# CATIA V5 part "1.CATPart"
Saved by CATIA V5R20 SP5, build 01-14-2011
Part number: 1
Bounding box of the stored display mesh (mm): x -106.5 to -93.5, y -24 to 26, z 3.5 to 16.5
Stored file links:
  F:\CAD\很靠后、\1.CATPart
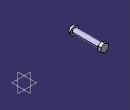
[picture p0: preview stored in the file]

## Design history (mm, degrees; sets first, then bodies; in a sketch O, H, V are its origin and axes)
Body1 (main body)
  Sketch1 on zx-plane, origin (0, 0, 0), H (-1, 0, 0), V (0, 0, 1)
    circle A1 centre (100, 10) radius 4
    radius A1 = 4
  Pad1: profile Sketch1, direction (0, 1, 0), length 21, mirrored extent
  Sketch2 on start face of Pad1, origin (0, -21, 0), H (1, 0, 0), V (0, 0, 1)
    circle A1 centre (-100, 10) radius 6.5
    radius A1 = 6.5
  Pad2: profile Sketch2, direction (0, -1, 0), length 3
  Sketch3 on end face of Pad1, origin (0, 21, 0), H (-1, 0, 0), V (0, 0, 1)
    point P1 (100, 10)
    point P2 (105.6292, 6.75)
    point P3 (105.6292, 13.25)
    point P4 (100, 16.5)
    point P5 (94.3708, 13.25)
    point P6 (94.3708, 6.75)
    point P7 (100, 3.5)
    point P8 (105.6292, 10)
    line L1 (105.6292, 6.75) -> (105.6292, 13.25)
    line L2 (105.6292, 13.25) -> (100, 16.5)
    line L3 (100, 16.5) -> (94.3708, 13.25)
    line L4 (94.3708, 13.25) -> (94.3708, 6.75)
    line L5 (94.3708, 6.75) -> (100, 3.5)
    line L6 (100, 3.5) -> (105.6292, 6.75)
    construction line L7 (100, 10) -> (105.6292, 10)
    construction circle A1 centre (100, 10) radius 6.5
    construction arc A2 centre (94.3708, 6.75) radius 6.5 from (94.3708, 13.25) to (100, 3.5) cw
    construction arc A3 centre (105.6292, 13.25) radius 6.5 from (100, 16.5) to (105.6292, 6.75) ccw
    radius A1 = 6.5
    coincidence: A1 P2, A1 P3, A1 P4, A1 P5, A1 P6, A1 P7, A2 P1, A3 P1
    midpoint: P8 L1
    parallelism: L1 L4
  Pad3: profile Sketch3, direction (0, 1, 0), length 5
